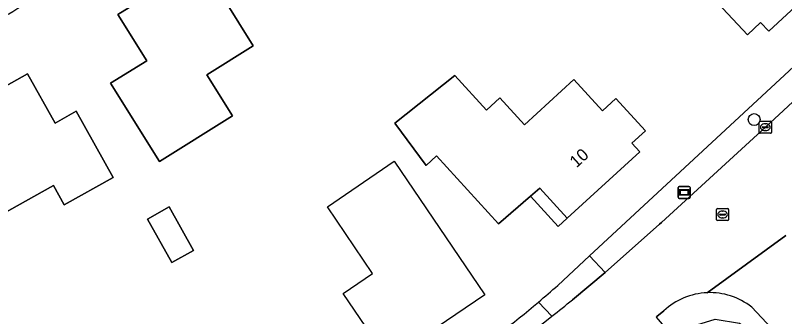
# Model space of a CAD drawing. Extents: x 162661 to 163484, y 380247 to 381230.
# Drawn here: x 163230.7 to 163294.2, y 380885.6 to 380910.4 of the extents above; entities that cross this region are included whole.
import ezdxf

# ---------------------------------------------------------------- set-up
doc = ezdxf.new("R2010")
doc.units = 0
for name, color, linetype in [('IMGEO_Berm_groen', 7, 'Continuous'), ('IMGEO_Boom', 7, 'Continuous'), ('IMGEO_Erf', 7, 'Continuous'), ('IMGEO_Groenvoorziening', 7, 'Continuous'), ('IMGEO_Kolk', 7, 'Continuous'), ('IMGEO_Pand', 7, 'Continuous'), ('IMGEO_Pand_nummerreeks', 7, 'Continuous'), ('IMGEO_Pand_overbouw', 7, 'Continuous'), ('IMGEO_Pand_vergunning_verleend', 7, 'Continuous'), ('IMGEO_Rijbaan_lokaal_gesloten', 7, 'Continuous'), ('IMGEO_Rioolput', 7, 'Continuous'), ('IMGEO_Straatnaambord', 7, 'Continuous'), ('IMGEO_Voetpad_open', 7, 'Continuous')]:
    doc.layers.add(name, color=color, linetype=linetype)

msp = doc.modelspace()

# ---------------------------------------------------------------- linework, layer by layer
at = {"layer": 'IMGEO_Berm_groen'}
msp.add_lwpolyline([(163292.603, 380901.179), (163303.421, 380911.205), (163303.486, 380911.264), (163302.041, 380912.777), (163278.098, 380890.562), (163279.38, 380889.205), (163283.878, 380893.181), (163284.042, 380893.331)], close=True, dxfattribs=at)
at = {"layer": 'IMGEO_Boom'}
msp.add_circle((163291.681, 380901.811), 0.489, dxfattribs=at)
at = {"layer": 'IMGEO_Erf'}
for points in [[(163278.098, 380890.562), (163302.041, 380912.777), (163305.328, 380915.802), (163315.837, 380925.681), (163316.494, 380926.299), (163317.332, 380927.055), (163320.579, 380929.984), (163321.057, 380930.657), (163321.299, 380931.564), (163321.184, 380932.515), (163320.761, 380933.306), (163296.884, 380958.739), (163295.699, 380959.641), (163294.252, 380959.688), (163293.024, 380958.913), (163283.361, 380949.868), (163280.252, 380946.958), (163279.693, 380946.435), (163279.155, 380946.024), (163267.646, 380936.418), (163264.752, 380934.006)], [(163275.479, 380888.133), (163278.098, 380890.562)]]:
    msp.add_lwpolyline(points, dxfattribs=at)
for points in [[(163289.384, 380920.952), (163294.56, 380925.767), (163299.721, 380920.22), (163297.196, 380917.871), (163296.437, 380917.165), (163298.814, 380914.61), (163292.897, 380909.095), (163292.215, 380909.827), (163291.121, 380908.79), (163288.672, 380911.424), (163289.774, 380912.45), (163287.391, 380915.013), (163291.421, 380918.761)], [(163238.587, 380904.814), (163241.56, 380906.665), (163239.179, 380910.486), (163242.132, 380912.327), (163241.604, 380913.175), (163245.538, 380915.627), (163246.066, 380914.775), (163247.346, 380915.572), (163249.25, 380912.514), (163247.967, 380911.716), (163250.351, 380907.884), (163246.52, 380905.499), (163248.629, 380902.11), (163242.607, 380898.36)], [(163225.048, 380901.833), (163231.725, 380905.584), (163234.007, 380901.521), (163235.734, 380902.491), (163238.8, 380897.033), (163234.763, 380894.766), (163233.866, 380896.363), (163229.499, 380893.91), (163227.497, 380897.474)], [(163266.983, 380905.437), (163269.593, 380902.584), (163270.701, 380903.597), (163272.724, 380901.386), (163276.794, 380905.109), (163279.161, 380902.521), (163280.275, 380903.541), (163282.703, 380900.887), (163281.591, 380899.869), (163282.254, 380899.144), (163276.25, 380893.676), (163274.001, 380896.146), (163273.236, 380895.486), (163270.598, 380893.212), (163265.473, 380898.815), (163264.612, 380898.027), (163262.04, 380901.516)], [(163241.619, 380893.598), (163243.417, 380894.599), (163245.417, 380891.005), (163243.636, 380890.014)]]:
    msp.add_lwpolyline(points, close=True, dxfattribs=at)
for centre, radius, start, end in [((163136.135, 381069.59), 184.779, 300.35123, 301.32631), ((163223.125, 380946.96), 78.75, 310.12843, 311.66759), ((163223.851, 380946.105), 77.628, 298.02504, 310.12611)]:
    msp.add_arc(centre, radius, start, end, dxfattribs=at)
at = {"layer": 'IMGEO_Groenvoorziening'}
for points in [[(163274.995, 380885.591), (163273.88, 380886.748)], [(163284.223, 380886.026), (163283.657, 380885.571), (163283.589, 380885.517), (163284.72, 380884.199), (163288.45, 380885.355), (163290.458, 380885.002), (163291.39, 380884.383), (163319.158, 380854.89)], [(163320.515, 380855.443), (163308.103, 380868.558), (163293.121, 380884.595), (163291.49, 380886.324), (163291.476, 380886.339)]]:
    msp.add_lwpolyline(points, dxfattribs=at)
for centre, radius, start, end in [((163288.028, 380881.973), 5.559, 92.44253, 133.18887), ((163288.033, 380881.969), 5.563, 51.76621, 92.49638), ((163223.851, 380946.105), 77.628, 298.02504, 310.12611), ((163122.174, 381079.082), 246.563, 305.54005, 308.30195)]:
    msp.add_arc(centre, radius, start, end, dxfattribs=at)
at = {"layer": 'IMGEO_Kolk'}
for p, q in [((163292.102, 380900.753), (163292.102, 380901.605)), ((163292.177, 380901.679), (163293.029, 380901.679)), ((163293.103, 380901.605), (163293.103, 380900.753)), ((163292.361, 380901.173), (163292.361, 380901.185)), ((163292.799, 380901.136), (163292.401, 380901.136)), ((163292.404, 380901.222), (163292.802, 380901.222)), ((163292.59, 380901.459), (163292.615, 380901.459)), ((163292.845, 380901.185), (163292.845, 380901.173)), ((163293.029, 380900.679), (163292.177, 380900.679)), ((163292.613, 380900.899), (163292.588, 380900.899))]:
    msp.add_line(p, q, dxfattribs=at)
for points in [[(163292.102, 380900.753), (163292.102, 380901.605)], [(163292.177, 380901.679), (163293.029, 380901.679)], [(163293.103, 380901.605), (163293.103, 380900.753)], [(163293.029, 380900.679), (163292.177, 380900.679)]]:
    msp.add_lwpolyline(points, dxfattribs=at)
for centre, radius, start, end in [((163292.179, 380901.603), 0.0765, 91.55205, 178.44795), ((163292.179, 380901.603), 0.0765, 91.55205, 178.44795), ((163293.027, 380901.603), 0.0765, 1.55205, 88.44795), ((163293.027, 380901.603), 0.0765, 1.55205, 88.44795), ((163292.401, 380901.182), 0.0403, 85.87752, 175.75265), ((163292.398, 380901.172), 0.0366, 178.93798, 274.71019), ((163292.802, 380901.179), 0.043, 264.86636, 352.45326), ((163292.806, 380901.184), 0.0386, 1.73085, 96.63898), ((163292.179, 380900.755), 0.0765, 181.55205, 268.44795), ((163292.179, 380900.755), 0.0765, 181.55205, 268.44795), ((163293.027, 380900.755), 0.0765, 271.55205, 358.44795), ((163293.027, 380900.755), 0.0765, 271.55205, 358.44795)]:
    msp.add_arc(centre, radius, start, end, dxfattribs=at)
for centre, major_axis, ratio, start_param, end_param in [((163292.589, 380901.179), (-0.387, 0.002), 0.722429, 4.712389, 7.853982), ((163292.614, 380901.179), (-0.39, 0.002), 0.717154, 1.570796, 4.712389)]:
    msp.add_ellipse(centre, major_axis=major_axis, ratio=ratio, start_param=start_param, end_param=end_param, dxfattribs=at)
at = {"layer": 'IMGEO_Pand'}
for points in [[(163298.814, 380914.61), (163296.437, 380917.165), (163297.196, 380917.871), (163299.721, 380920.22), (163294.56, 380925.767), (163289.384, 380920.952), (163291.421, 380918.761), (163287.391, 380915.013), (163289.774, 380912.45), (163288.672, 380911.424), (163291.121, 380908.79), (163292.215, 380909.827), (163292.897, 380909.095)], [(163238.587, 380904.814), (163242.607, 380898.36), (163248.629, 380902.11), (163246.52, 380905.499), (163250.351, 380907.884), (163247.967, 380911.716), (163249.25, 380912.514), (163247.346, 380915.572), (163246.066, 380914.775), (163245.538, 380915.627), (163241.604, 380913.175), (163242.132, 380912.327), (163239.179, 380910.486), (163241.56, 380906.665)], [(163234.007, 380901.521), (163231.725, 380905.584), (163225.048, 380901.833), (163227.497, 380897.474), (163229.499, 380893.91), (163233.866, 380896.363), (163234.763, 380894.766), (163238.8, 380897.033), (163235.734, 380902.491)], [(163282.254, 380899.144), (163281.591, 380899.869), (163282.703, 380900.887), (163280.275, 380903.541), (163279.161, 380902.521), (163276.794, 380905.109), (163272.724, 380901.386), (163270.701, 380903.597), (163269.593, 380902.584), (163266.983, 380905.437), (163262.04, 380901.516), (163264.612, 380898.027), (163265.473, 380898.815), (163270.598, 380893.212), (163273.236, 380895.486), (163274.001, 380896.146), (163276.25, 380893.676)], [(163241.619, 380893.598), (163243.636, 380890.014), (163245.417, 380891.005), (163243.417, 380894.599)]]:
    msp.add_lwpolyline(points, close=True, dxfattribs=at)
at = {"layer": 'IMGEO_Pand_overbouw'}
msp.add_lwpolyline([(163276.25, 380893.676), (163274.001, 380896.146), (163273.236, 380895.486), (163275.503, 380892.997)], close=True, dxfattribs=at)
at = {"layer": 'IMGEO_Pand_vergunning_verleend'}
msp.add_lwpolyline([(163256.465, 380894.62), (163261.984, 380898.37), (163269.466, 380887.356), (163261.512, 380881.952), (163257.765, 380887.467), (163260.201, 380889.122)], close=True, dxfattribs=at)
at = {"layer": 'IMGEO_Rijbaan_lokaal_gesloten'}
for points in [[(163321.7, 380928.048), (163321.019, 380927.42), (163318.596, 380925.187), (163317.82, 380924.471), (163310.229, 380917.474), (163306.754, 380914.26), (163303.486, 380911.264), (163303.421, 380911.205), (163292.603, 380901.179), (163284.042, 380893.331), (163283.878, 380893.181), (163279.38, 380889.205), (163276.68, 380886.933)], [(163294.297, 380892.257), (163287.791, 380887.527)], [(163287.791, 380887.527), (163294.297, 380892.257)], [(163291.476, 380886.339), (163291.49, 380886.324), (163293.121, 380884.595), (163308.103, 380868.558), (163320.515, 380855.443), (163324.069, 380858.662), (163314.835, 380868.497), (163296.565, 380887.892)], [(163283.589, 380885.517), (163283.657, 380885.571), (163284.223, 380886.026)]]:
    msp.add_lwpolyline(points, dxfattribs=at)
for centre, radius, start, end in [((163288.028, 380881.973), 5.559, 92.44253, 133.18887), ((163288.033, 380881.969), 5.563, 51.76621, 92.49638), ((163131.236, 381067.821), 232.109, 308.26932, 308.80106), ((163122.174, 381079.082), 246.563, 305.54005, 308.30195)]:
    msp.add_arc(centre, radius, start, end, dxfattribs=at)
at = {"layer": 'IMGEO_Rioolput'}
for p, q in [((163288.574, 380893.55), (163288.574, 380894.402)), ((163288.649, 380894.476), (163289.501, 380894.476)), ((163288.833, 380893.97), (163288.833, 380893.982)), ((163288.876, 380894.019), (163289.274, 380894.019)), ((163289.062, 380894.256), (163289.087, 380894.256)), ((163289.317, 380893.982), (163289.317, 380893.97)), ((163289.575, 380894.402), (163289.575, 380893.55)), ((163289.501, 380893.476), (163288.649, 380893.476)), ((163289.271, 380893.933), (163288.873, 380893.933)), ((163289.085, 380893.696), (163289.06, 380893.696))]:
    msp.add_line(p, q, dxfattribs=at)
for points in [[(163288.574, 380893.55), (163288.574, 380894.402)], [(163288.649, 380894.476), (163289.501, 380894.476)], [(163289.575, 380894.402), (163289.575, 380893.55)], [(163289.501, 380893.476), (163288.649, 380893.476)]]:
    msp.add_lwpolyline(points, dxfattribs=at)
for centre, radius, start, end in [((163288.651, 380894.4), 0.0765, 91.55205, 178.44795), ((163288.651, 380894.4), 0.0765, 91.55205, 178.44795), ((163288.873, 380893.979), 0.0403, 85.87752, 175.75265), ((163288.87, 380893.969), 0.0366, 178.93798, 274.71019), ((163289.274, 380893.976), 0.043, 264.86636, 352.45326), ((163289.278, 380893.981), 0.0386, 1.73085, 96.63898), ((163289.499, 380894.4), 0.0765, 1.55205, 88.44795), ((163289.499, 380894.4), 0.0765, 1.55205, 88.44795), ((163288.651, 380893.552), 0.0765, 181.55205, 268.44795), ((163288.651, 380893.552), 0.0765, 181.55205, 268.44795), ((163289.499, 380893.552), 0.0765, 271.55205, 358.44795), ((163289.499, 380893.552), 0.0765, 271.55205, 358.44795)]:
    msp.add_arc(centre, radius, start, end, dxfattribs=at)
for centre, major_axis, ratio, start_param, end_param in [((163289.061, 380893.976), (-0.387, 0.002), 0.722429, 4.712389, 7.853982), ((163289.086, 380893.976), (-0.39, 0.002), 0.717154, 1.570796, 4.712389)]:
    msp.add_ellipse(centre, major_axis=major_axis, ratio=ratio, start_param=start_param, end_param=end_param, dxfattribs=at)
at = {"layer": 'IMGEO_Straatnaambord'}
for p, q in [((163285.399, 380895.399), (163285.399, 380896.199)), ((163285.399, 380896.199), (163285.399, 380895.399)), ((163285.499, 380896.299), (163286.289, 380896.299)), ((163286.289, 380896.299), (163285.499, 380896.299)), ((163286.389, 380896.199), (163286.389, 380895.399)), ((163286.389, 380895.399), (163286.389, 380896.199)), ((163286.289, 380895.299), (163285.499, 380895.299)), ((163285.499, 380895.299), (163286.289, 380895.299))]:
    msp.add_line(p, q, dxfattribs=at)
for points in [[(163285.5, 380896.031), (163286.288, 380896.031), (163286.288, 380895.567), (163285.5, 380895.567), (163285.5, 380896.031)], [(163285.565, 380895.966), (163285.565, 380895.632), (163286.223, 380895.632), (163286.223, 380895.966), (163285.565, 380895.966)]]:
    msp.add_lwpolyline(points, dxfattribs=at)
for centre, start, end in [((163285.499, 380896.199), 90, 180), ((163285.499, 380896.199), 90, 180), ((163286.289, 380896.199), 0, 90), ((163286.289, 380896.199), 360, 90), ((163285.499, 380895.399), 180, 270), ((163285.499, 380895.399), 180, 270), ((163286.289, 380895.399), 270, 0), ((163286.289, 380895.399), 270, 0)]:
    msp.add_arc(centre, 0.1, start, end, dxfattribs=at)
at = {"layer": 'IMGEO_Voetpad_open'}
for points in [[(163279.38, 380889.205), (163278.098, 380890.562), (163275.479, 380888.133)], [(163276.68, 380886.933), (163279.38, 380889.205)], [(163273.88, 380886.748), (163274.995, 380885.591)]]:
    msp.add_lwpolyline(points, dxfattribs=at)
for centre, radius, start, end in [((163136.135, 381069.59), 184.779, 300.35123, 301.32631), ((163223.125, 380946.96), 78.75, 310.12843, 311.66759), ((163131.236, 381067.821), 232.109, 308.26932, 308.80106)]:
    msp.add_arc(centre, radius, start, end, dxfattribs=at)

# ---------------------------------------------------------------- texts
at = {"layer": 'IMGEO_Pand_nummerreeks'}
msp.add_text('10', height=1, rotation=42.31866, dxfattribs=at).set_placement((163277.013, 380897.78))

doc.saveas('drawing.dxf')
